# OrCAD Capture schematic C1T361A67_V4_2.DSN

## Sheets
1 001_LOG: title: TELINK; rev: V4.2; note: C1T361A67
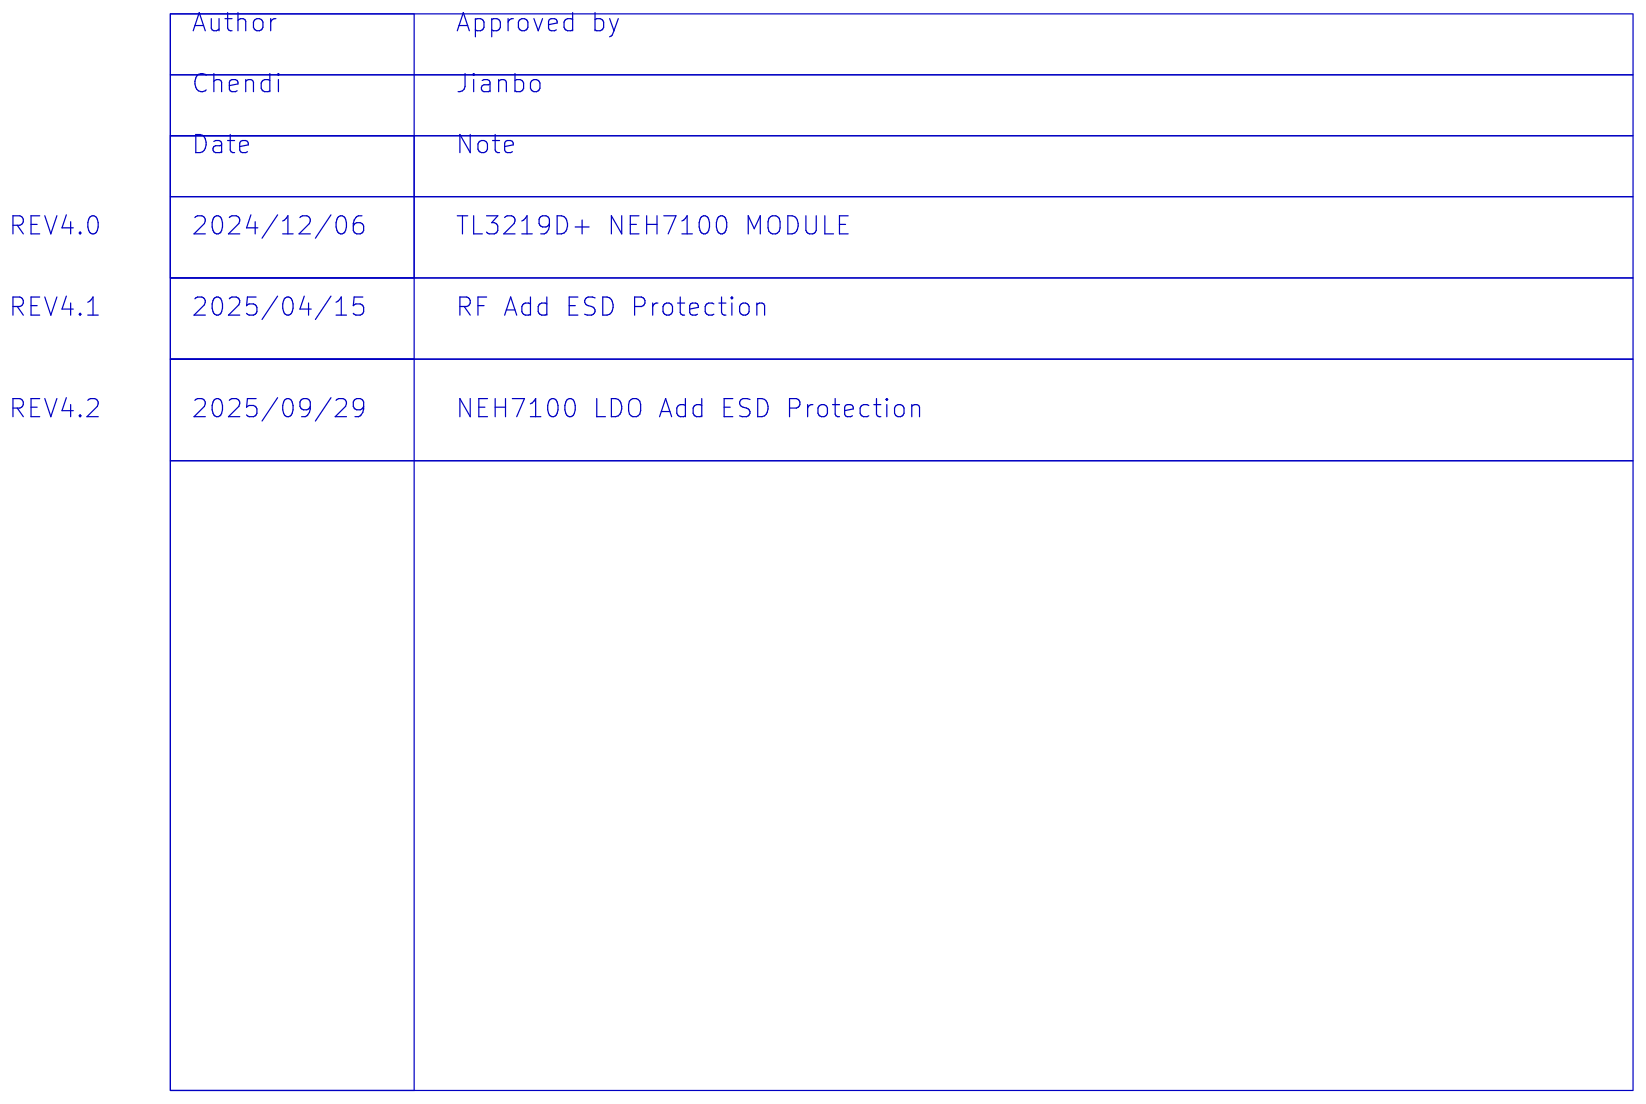
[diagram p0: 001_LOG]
2 002_TL3219D: size A4
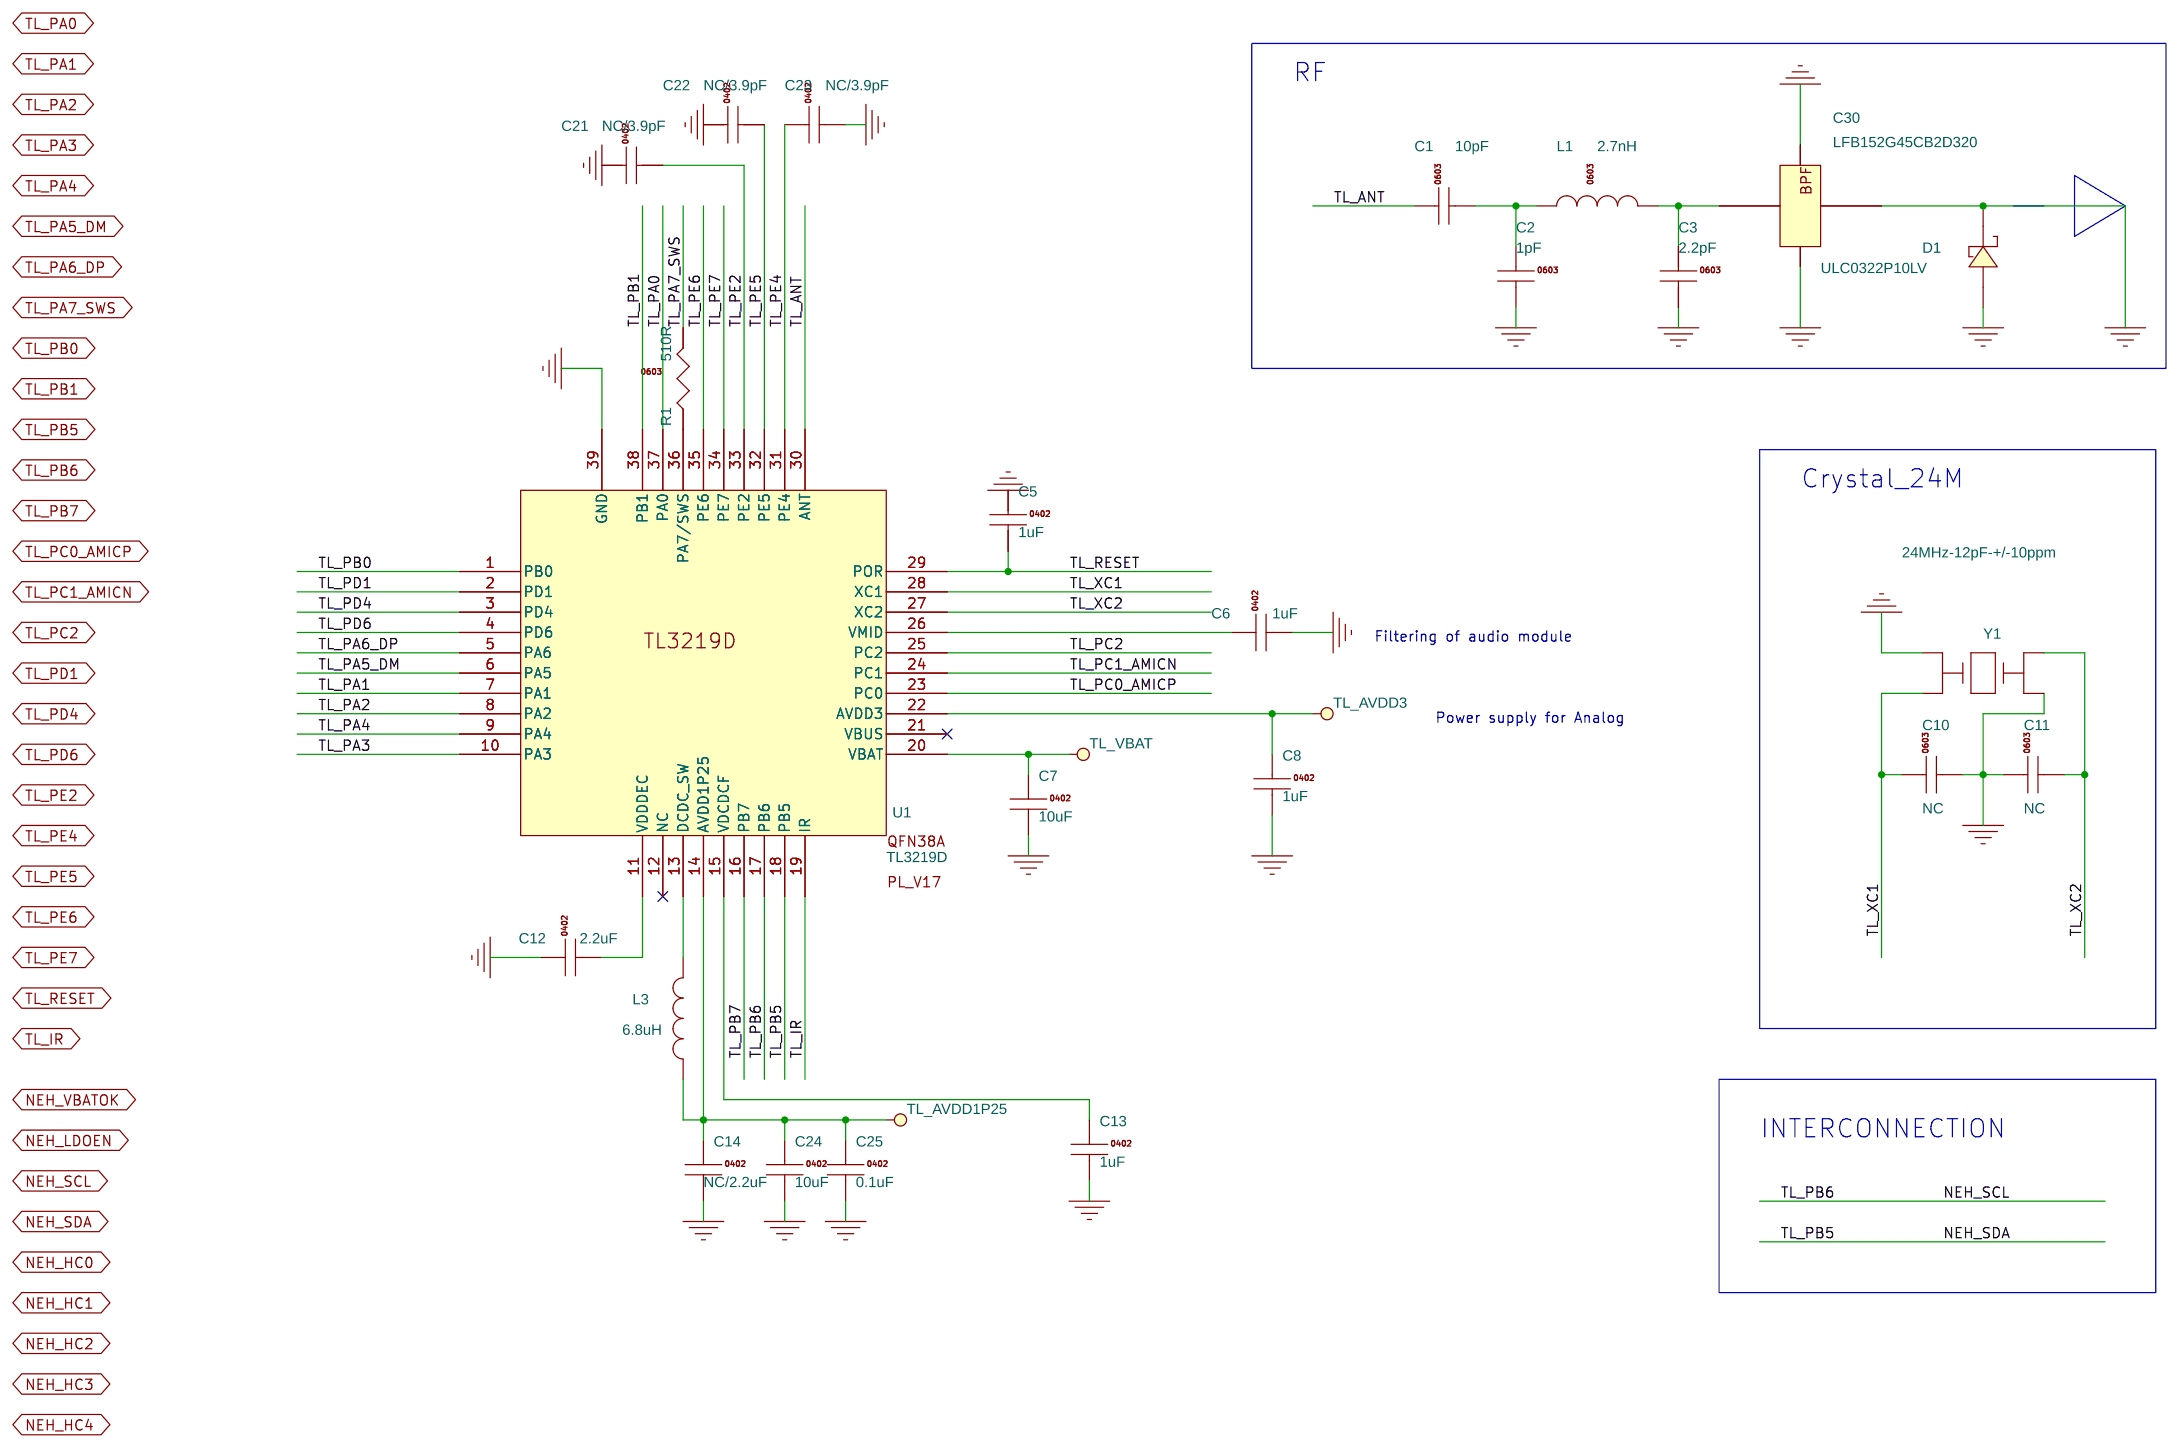
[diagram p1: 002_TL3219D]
3 003_NEH7100: size A4
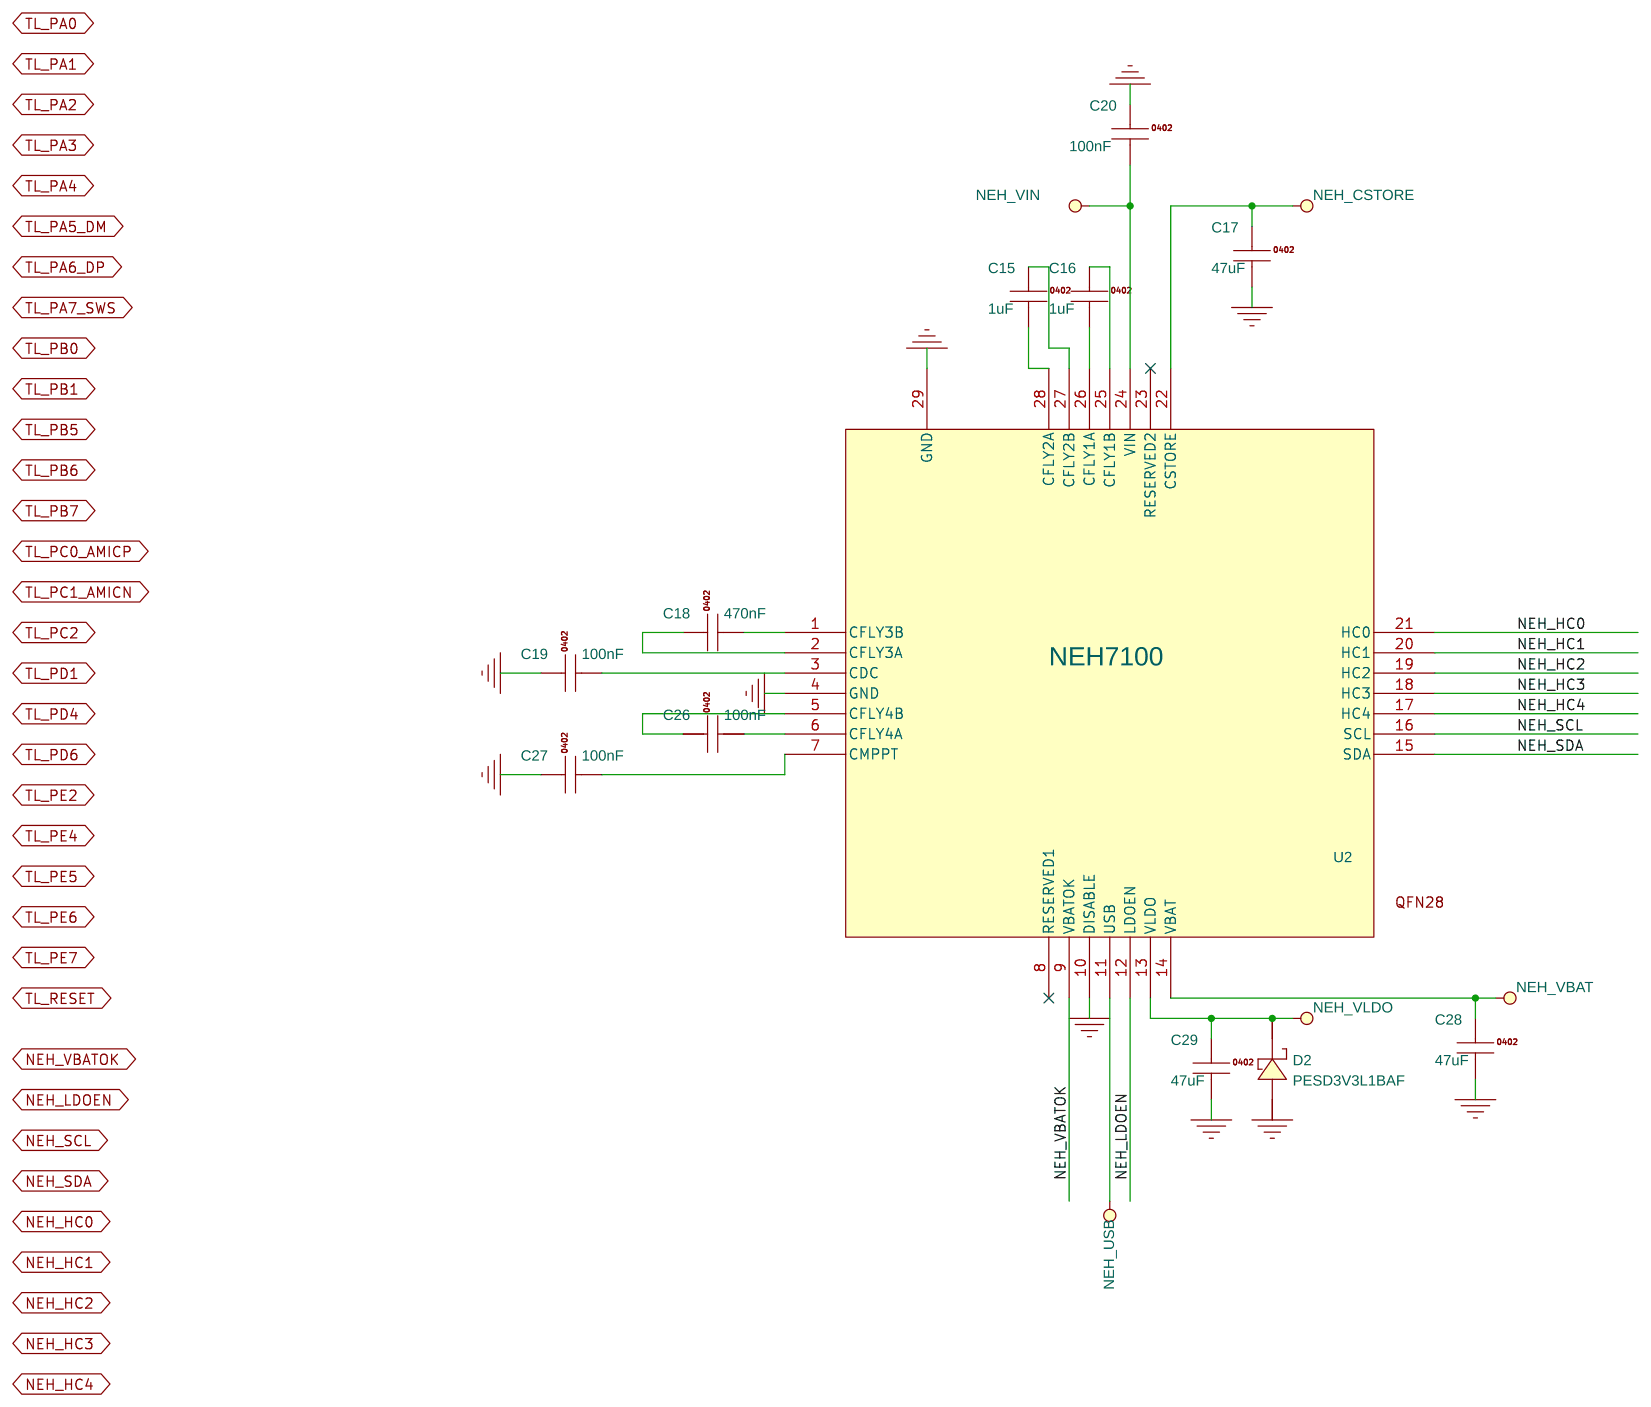
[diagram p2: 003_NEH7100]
4 004_MODULE: size A4
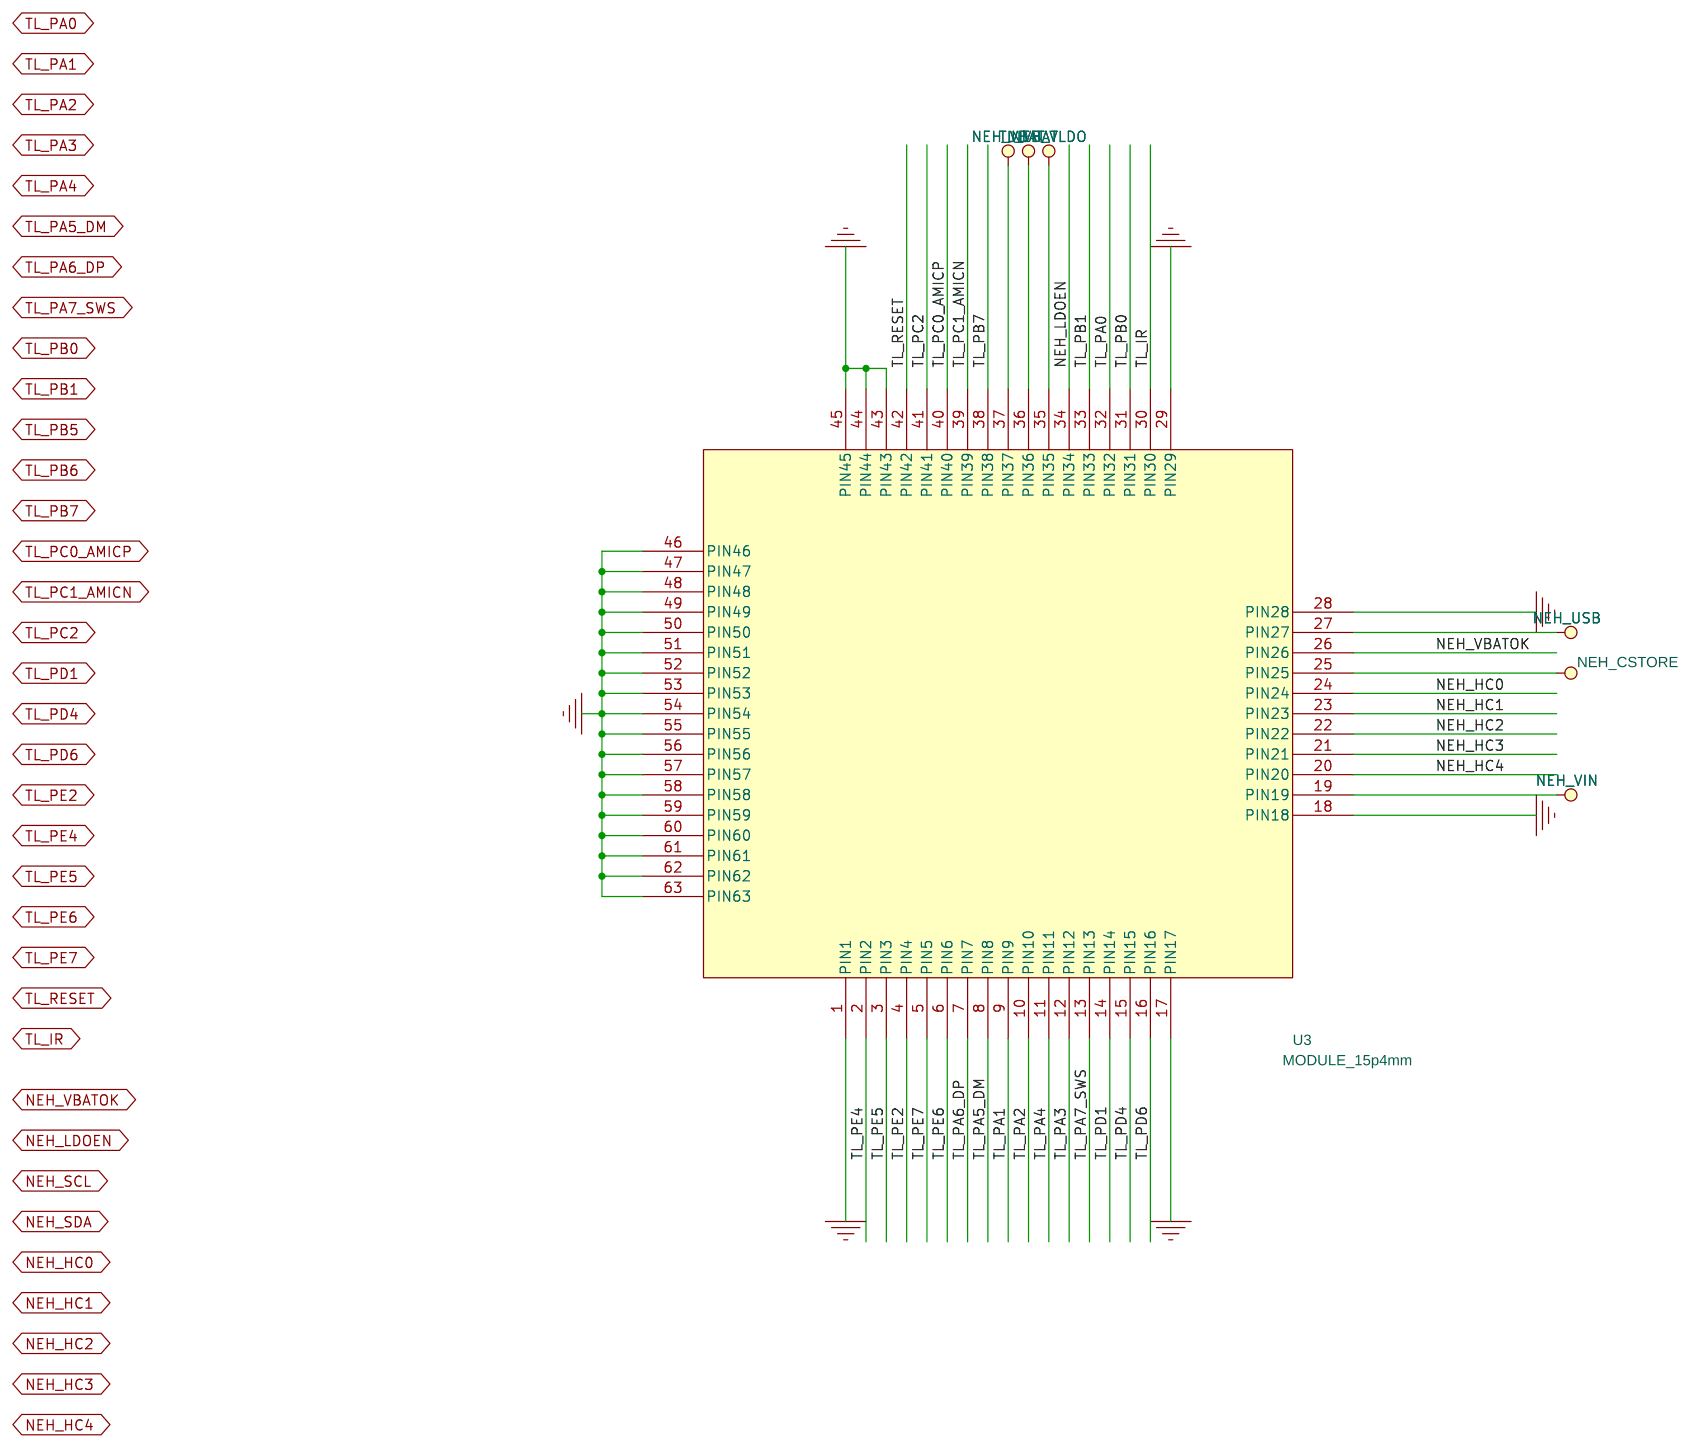
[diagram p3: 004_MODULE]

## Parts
sheet 002_TL3219D
C1  10pF  [0201]
C2  1pF  [0201]
C3  2.2pF  [0201]
C5  1uF  [0201]
C6  1uF  [0201]
C7  10uF  [0402]
C8  1uF  [0201]
C10  NC  [0201]
C11  NC  [0201]
C12  2.2uF  [0201]
C13  1uF  [0201]
C14  NC/2.2uF  [0201]
C21  NC/3.9pF  [0201]
C22  NC/3.9pF  [0201]
C23  NC/3.9pF  [0201]
C24  10uF  [0402]
C25  0.1uF  [0201]
C30  LFB152G45CB2D320  [0402_d]
D1  ULC0322P10LV  [0201]
L1  2.7nH  [0201]
L3  6.8uH  [1008L]
R1  510R  [0201]
U1  TL3219D  [qfn_4x4_38pin_0p35_2p9x2p9]
Y1  24MHz-12pF-+/-10ppm  [osccc160x200x065]
sheet 003_NEH7100
C15  1uF  [0402]
C16  1uF  [0402]
C17  47uF  [0603C]
C18  470nF  [0402]
C19  100nF  [0402]
C20  100nF  [0402]
C26  100nF  [0402]
C27  100nF  [0402]
C28  47uF  [0603C]
C29  47uF  [0603C]
D2  PESD3V3L1BAF  [SOD323]
U2  NEH7100  [qfn_4x4_28pin_0p4_2p5x2p5]
sheet 004_MODULE
U3  MODULE_15p4mm  [module_buteo_eh_1211]

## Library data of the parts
C1-C3 C10 C11 = C1608_NC
C5-C8 C12-C29 = C1005X5R1C104K
C30 = C1608_NC_4
D1 D2 = DIODE_SCHOTTKY_0
L1 = MLK1608_000R
L3 = IND_0
R1 = RS0603K330JT
U1 = TL3219D
Y1 = CRYSTAL4_SM_0
U2 = TLSR9517C_9
U3 = TLSR8868ET48_14

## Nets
GND: C2.2 C3.2 C5.1 C6.2 C7.2 C8.2 C10.2 C11.1 C12.1 C13.2 C14.2 C17.2 C19.1 C20.1 C21.1 C22.1 C23.2 C24.2 C25.2 C27.1 C28.2 C29.2 C30.1 C30.2 C30.3 D1.1(ANODE) D1.2(CATHODE) D2.1(ANODE) U1.39(GND) U2.4(GND) U2.10(DISABLE) U2.29(GND) U3.1(PIN1) U3.17(PIN17) U3.18(PIN18) U3.28(PIN28) U3.29(PIN29) U3.43(PIN43) U3.44(PIN44) U3.45(PIN45) U3.46(PIN46) U3.47(PIN47) U3.48(PIN48) U3.49(PIN49) U3.50(PIN50) U3.51(PIN51) U3.52(PIN52) U3.53(PIN53) U3.54(PIN54) U3.55(PIN55) U3.56(PIN56) U3.57(PIN57) U3.58(PIN58) U3.59(PIN59) U3.60(PIN60) U3.61(PIN61) U3.62(PIN62) U3.63(PIN63) Y1.2 Y1.4
NEH_CSTORE: C17.1 U2.22(CSTORE) U3.25(PIN25)
NEH_HC0: U2.21(HC0)
NEH_HC0 (page 004_MODULE): U3.24(PIN24)
NEH_HC1: U2.20(HC1)
NEH_HC1 (page 004_MODULE): U3.23(PIN23)
NEH_HC2: U2.19(HC2)
NEH_HC2 (page 004_MODULE): U3.22(PIN22)
NEH_HC3: U2.18(HC3)
NEH_HC3 (page 004_MODULE): U3.21(PIN21)
NEH_HC4: U2.17(HC4)
NEH_HC4 (page 004_MODULE): U3.20(PIN20)
NEH_LDOEN: U2.12(LDOEN)
NEH_LDOEN (page 004_MODULE): U3.34(PIN34)
NEH_SCL: U1.17(PB6)
NEH_SCL (page 003_NEH7100): U2.16(SCL)
NEH_SDA: U1.18(PB5)
NEH_SDA (page 003_NEH7100): U2.15(SDA)
NEH_USB: U2.11(USB) U3.27(PIN27)
NEH_VBAT: C28.1 U2.14(VBAT) U3.37(PIN37)
NEH_VBATOK: U2.9(VBATOK)
NEH_VBATOK (page 004_MODULE): U3.26(PIN26)
NEH_VIN: C20.2 U2.24(VIN) U3.19(PIN19)
NEH_VLDO: C29.1 D2.2(CATHODE) U2.13(VLDO) U3.35(PIN35)
TL_ANT: C1.1 U1.30(ANT)
TL_AVDD1P25: C14.1 C24.1 C25.1 L3.1 U1.14(AVDD1P25)
TL_AVDD3: C8.1 U1.22(AVDD3)
TL_IR: U1.19(IR)
TL_IR (page 004_MODULE): U3.30(PIN30)
TL_PA0: U1.37(PA0)
TL_PA0 (page 004_MODULE): U3.32(PIN32)
TL_PA1: U1.7(PA1)
TL_PA1 (page 004_MODULE): U3.9(PIN9)
TL_PA2: U1.8(PA2)
TL_PA2 (page 004_MODULE): U3.10(PIN10)
TL_PA3: U1.10(PA3)
TL_PA3 (page 004_MODULE): U3.12(PIN12)
TL_PA4: U1.9(PA4)
TL_PA4 (page 004_MODULE): U3.11(PIN11)
TL_PA5_DM: U1.6(PA5)
TL_PA5_DM (page 004_MODULE): U3.8(PIN8)
TL_PA6_DP: U1.5(PA6)
TL_PA6_DP (page 004_MODULE): U3.7(PIN7)
TL_PA7_SWS: R1.1
TL_PA7_SWS (page 004_MODULE): U3.13(PIN13)
TL_PB0: U1.1(PB0)
TL_PB0 (page 004_MODULE): U3.31(PIN31)
TL_PB1: U1.38(PB1)
TL_PB1 (page 004_MODULE): U3.33(PIN33)
TL_PB7: U1.16(PB7)
TL_PB7 (page 004_MODULE): U3.38(PIN38)
TL_PC0_AMICP: U1.23(PC0)
TL_PC0_AMICP (page 004_MODULE): U3.40(PIN40)
TL_PC1_AMICN: U1.24(PC1)
TL_PC1_AMICN (page 004_MODULE): U3.39(PIN39)
TL_PC2: U1.25(PC2)
TL_PC2 (page 004_MODULE): U3.41(PIN41)
TL_PD1: U1.2(PD1)
TL_PD1 (page 004_MODULE): U3.14(PIN14)
TL_PD4: U1.3(PD4)
TL_PD4 (page 004_MODULE): U3.15(PIN15)
TL_PD6: U1.4(PD6)
TL_PD6 (page 004_MODULE): U3.16(PIN16)
TL_PE2: C21.2 U1.33(PE2)
TL_PE2 (page 004_MODULE): U3.4(PIN4)
TL_PE4: C23.1 U1.31(PE4)
TL_PE4 (page 004_MODULE): U3.2(PIN2)
TL_PE5: C22.2 U1.32(PE5)
TL_PE5 (page 004_MODULE): U3.3(PIN3)
TL_PE6: U1.35(PE6)
TL_PE6 (page 004_MODULE): U3.6(PIN6)
TL_PE7: U1.34(PE7)
TL_PE7 (page 004_MODULE): U3.5(PIN5)
TL_RESET: C5.2 U1.29(POR)
TL_RESET (page 004_MODULE): U3.42(PIN42)
TL_VBAT: C7.1 U1.20(VBAT) U3.36(PIN36)
TL_XC1: C10.1 U1.28(XC1) Y1.3
TL_XC2: C11.2 U1.27(XC2) Y1.1
N20494255: C1.2 C2.1 L1.1
N20494385: C3.1 C30.4 L1.2
N20502827: C6.1 U1.26(VMID)
N20503268: C12.2 U1.11(VDDDEC)
N20503276: C13.1 U1.15(VDCDCF)
N20503917: L3.2 U1.13(DCDC_SW)
N20508843: C16.1 U2.25(CFLY1B)
N20508848: C16.2 U2.26(CFLY1A)
N20508856: C15.1 U2.27(CFLY2B)
N20508888: C15.2 U2.28(CFLY2A)
N20508941: C18.2 U2.1(CFLY3B)
N20508944: C18.1 U2.2(CFLY3A)
N20508953: C26.1 U2.5(CFLY4B)
N20508962: C26.2 U2.6(CFLY4A)
N20508983: C19.2 U2.3(CDC)
N20515790: C27.2 U2.7(CMPPT)
N20527553: R1.2 U1.36(PA7/SWS)

Not connected (* = marked no-connect by the designer): U1 12(NC)* 21(VBUS)*; U2 8(RESERVED1)* 23(RESERVED2)*

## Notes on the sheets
sheet 1
- Author
- Approved by
- Chendi
- Jianbo
- Date
- Note
- REV4.0
- 2024/12/06
- TL3219D+ NEH7100 MODULE
- REV4.1
- 2025/04/15
- RF Add ESD Protection
- REV4.2
- 2025/09/29
- NEH7100 LDO Add ESD Protection
sheet 2
- RF
- Crystal_24M
- Filtering of audio module
- Power supply for Analog
- INTERCONNECTION
